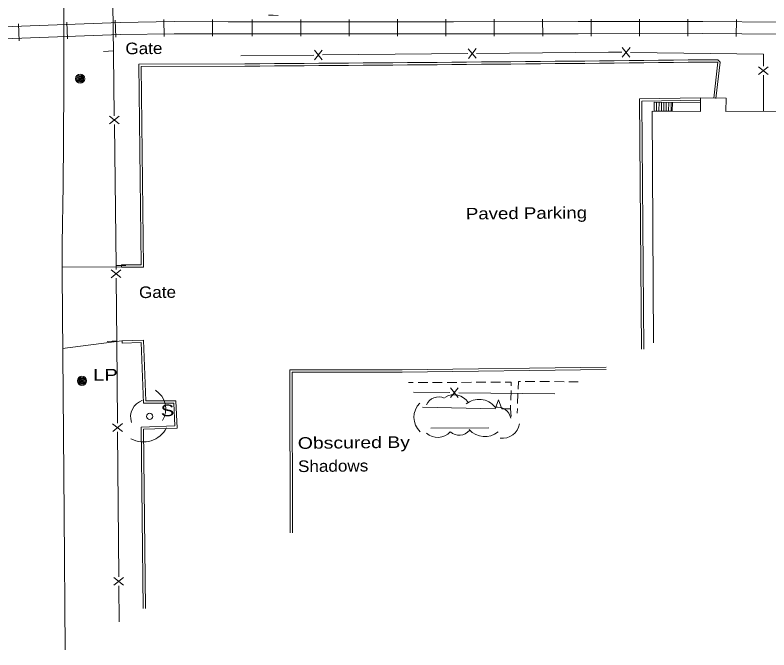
# Model space of a CAD drawing. Extents: x 2361284 to 2366480, y 6976556 to 6985346.
# Drawn here: x 2361689.4 to 2362001, y 6976992.8 to 6977255.3 of the extents above; entities that cross this region are included whole.
import ezdxf

# ---------------------------------------------------------------- set-up
doc = ezdxf.new("R2010")
doc.units = 0
doc.header["$LTSCALE"] = 1.9
for name, color, linetype, lineweight in [('11', 7, 'Continuous', 13), ('16', 7, 'Continuous', 13), ('19', 7, 'Continuous', 13), ('26', 7, 'Continuous', 13), ('28', 7, 'Continuous', 13), ('29', 7, 'Continuous', 13), ('3', 7, 'Continuous', 13), ('31', 7, 'Continuous', 13), ('4', 7, 'Continuous', 13), ('5', 7, 'Continuous', 13), ('7', 7, 'Continuous', 13), ('9', 7, 'Continuous', 13)]:
    doc.layers.add(name, color=color, linetype=linetype, lineweight=lineweight)

msp = doc.modelspace()

# ---------------------------------------------------------------- linework, layer by layer
at = {"layer": '11'}
msp.add_circle((2361745.02, 6977089.36), 1.3, dxfattribs=at)
at = {"layer": '16'}
for centre, radius, start, end in [((2361742.596, 6977092.433), 9.103, 328.01196, 58.01196), ((2361744.43, 6977089.118), 7.275, 108.25474, 198.25474), ((2361864.495, 6977091.789), 5.604, 65.33216, 155.33216), ((2361870.827, 6977091.313), 7.012, 32.34679, 122.34679), ((2361881.19, 6977087.978), 8.41, 39.00343, 129.00343), ((2361862.699, 6977089.017), 8.41, 135.70785, 225.70785), ((2361888.79, 6977087.607), 5.604, 10.97913, 100.97913), ((2361742.424, 6977089.717), 10.919, 242.07144, 332.07144), ((2361872.981, 6977087.197), 5.604, 229.38669, 319.38669), ((2361883.553, 6977089.37), 8.41, 220.60853, 310.60853), ((2361890.968, 6977087.35), 7.012, 261.38556, 351.38556), ((2361864.094, 6977087.684), 7.012, 227.98846, 317.98846)]:
    msp.add_arc(centre, radius, start, end, dxfattribs=at)
at = {"layer": '19'}
for p, q in [((2361852.002, 6977103.326), (2361854.002, 6977103.335)), ((2361856.002, 6977103.344), (2361860.002, 6977103.363)), ((2361862.002, 6977103.372), (2361866.003, 6977103.39)), ((2361868.003, 6977103.399), (2361872.003, 6977103.417)), ((2361874.003, 6977103.426), (2361878.002, 6977103.444)), ((2361880.002, 6977103.453), (2361884.002, 6977103.471)), ((2361886.002, 6977103.48), (2361890.003, 6977103.498)), ((2361900.311, 6977103.806), (2361904.311, 6977103.774)), ((2361906.31, 6977103.763), (2361910.312, 6977103.731)), ((2361912.312, 6977103.72), (2361916.313, 6977103.688)), ((2361918.313, 6977103.677), (2361922.093, 6977103.643)), ((2361894.397, 6977100.009), (2361894.285, 6977096.008)), ((2361897.147, 6977094.675), (2361897.279, 6977098.677)), ((2361894.224, 6977094.007), (2361894.179, 6977092.417)), ((2361897.005, 6977090.674), (2361897.076, 6977092.675))]:
    msp.add_line(p, q, dxfattribs=at)
for points in [[(2361892.003, 6977103.507), (2361894.503, 6977103.511), (2361894.458, 6977102.01)], [(2361897.35, 6977100.678), (2361897.45, 6977103.819), (2361898.311, 6977103.817)]]:
    msp.add_lwpolyline(points, dxfattribs=at)
at = {"layer": '26'}
msp.add_line((2361857.829, 6977093.181), (2361887.827, 6977092.547), dxfattribs=at)
for points in [[(2361887.827, 6977092.547), (2361889.223, 6977096.15), (2361890.588, 6977092.493)], [(2361890.598, 6977092.493), (2361894.179, 6977092.417), (2361894.398, 6977089.319)]]:
    msp.add_lwpolyline(points, dxfattribs=at)
at = {"layer": '28'}
for p, q in [((2361953.576, 6977219.288), (2361953.53, 6977215.708)), ((2361953.576, 6977219.288), (2361961.116, 6977219.2)), ((2361954.576, 6977219.278), (2361954.53, 6977215.697)), ((2361955.576, 6977219.267), (2361955.53, 6977215.687)), ((2361956.577, 6977219.247), (2361956.531, 6977215.666)), ((2361957.577, 6977219.236), (2361957.531, 6977215.656)), ((2361958.577, 6977219.226), (2361958.531, 6977215.645)), ((2361959.577, 6977219.215), (2361959.531, 6977215.635)), ((2361960.576, 6977219.195), (2361960.53, 6977215.614)), ((2361961.116, 6977219.2), (2361961.07, 6977215.62)), ((2361953.53, 6977215.708), (2361961.07, 6977215.62))]:
    msp.add_line(p, q, dxfattribs=at)
at = {"layer": '29'}
for p, q in [((2361710.807, 6977252.462), (2361711.063, 6977245.474)), ((2361730.801, 6977253.182), (2361731.047, 6977246.184)), ((2361750.908, 6977253.543), (2361751.025, 6977246.544)), ((2361771.019, 6977253.574), (2361771.005, 6977246.574)), ((2361787.471, 6977253.561), (2361787.477, 6977246.56)), ((2361807.472, 6977253.561), (2361807.478, 6977246.561)), ((2361827.472, 6977253.571), (2361827.479, 6977246.571)), ((2361847.474, 6977253.581), (2361847.481, 6977246.581)), ((2361867.475, 6977253.591), (2361867.482, 6977246.591)), ((2361887.476, 6977253.602), (2361887.482, 6977246.601)), ((2361907.476, 6977253.612), (2361907.482, 6977246.611)), ((2361927.477, 6977253.632), (2361927.484, 6977246.632)), ((2361947.478, 6977253.642), (2361947.475, 6977246.642)), ((2361967.479, 6977253.652), (2361967.476, 6977246.652)), ((2361987.532, 6977253.543), (2361987.469, 6977246.542)), ((2361690.813, 6977251.712), (2361691.079, 6977244.724))]:
    msp.add_line(p, q, dxfattribs=at)
for points in [[(2361502.388, 6977223.829), (2361520.924, 6977227.435), (2361539.462, 6977231.032), (2361564.028, 6977235.776), (2361588.624, 6977240.519), (2361605.934, 6977243.684), (2361623.379, 6977246.57), (2361638.949, 6977248.578), (2361654.61, 6977249.627), (2361678.726, 6977250.287), (2361680.815, 6977250.336), (2361706.777, 6977251.323), (2361732.821, 6977252.251), (2361755.178, 6977252.624), (2361777.5, 6977252.556)], [(2361777.48, 6977252.556), (2361824.032, 6977252.568), (2361870.585, 6977252.591), (2361922.127, 6977252.631), (2361973.699, 6977252.661), (2362006.034, 6977252.399), (2362038.331, 6977251.806)], [(2361503.334, 6977218.918), (2361521.871, 6977222.524), (2361540.409, 6977226.12), (2361564.975, 6977230.864), (2361589.541, 6977235.599), (2361606.791, 6977238.752), (2361624.106, 6977241.617), (2361639.437, 6977243.593), (2361654.838, 6977244.629), (2361667.906, 6977244.983), (2361680.972, 6977245.338), (2361706.955, 6977246.325), (2361732.948, 6977247.252), (2361755.206, 6977247.614), (2361777.477, 6977247.555)], [(2361777.477, 6977247.555), (2361824.029, 6977247.568), (2361870.582, 6977247.591), (2361922.124, 6977247.631), (2361973.676, 6977247.661), (2362005.961, 6977247.398), (2362038.238, 6977246.805)]]:
    msp.add_lwpolyline(points, dxfattribs=at)
at = {"layer": '3'}
for p, q in [((2361733.373, 6977151.022), (2361708.869, 6977151.269)), ((2361733.373, 6977151.022), (2361733.374, 6977151.982)), ((2361733.563, 6977120.561), (2361709.092, 6977117.408)), ((2361733.692, 6977119.612), (2361733.653, 6977120.572)), ((2361933.786, 6977109.694), (2361849.333, 6977108.561)), ((2361933.795, 6977108.734), (2361849.342, 6977107.601))]:
    msp.add_line(p, q, dxfattribs=at)
for points in [[(2361709.263, 6977380.134), (2361708.329, 6977367.291), (2361707.952, 6977360.87), (2361707.542, 6977351.237), (2361707.362, 6977341.602), (2361707.374, 6977336.784), (2361707.501, 6977329.848), (2361708.007, 6977315.976), (2361709.246, 6977288.229), (2361709.529, 6977274.351), (2361709.615, 6977226.968), (2361709.504, 6977203.277), (2361709.238, 6977185.014), (2361708.851, 6977160.664), (2361708.835, 6977148.488), (2361709.644, 6977048.779), (2361710.137, 6976992.762)], [(2361979.827, 6977236.889), (2361980.79, 6977235.819), (2361979.112, 6977220.881)], [(2361733.373, 6977151.022), (2361742.453, 6977151.018), (2361741.473, 6977234.033), (2361784.455, 6977234.202)], [(2361733.374, 6977151.982), (2361741.484, 6977151.979), (2361740.504, 6977234.994), (2361784.456, 6977235.162)], [(2361979.837, 6977235.929), (2361979.839, 6977235.93), (2361978.161, 6977220.992)], [(2361972.699, 6977221.05), (2361947.491, 6977220.731), (2361948.276, 6977117.192)], [(2361972.708, 6977220.09), (2361948.46, 6977219.78), (2361949.236, 6977117.202)], [(2361743.264, 6977009.947), (2361742.55, 6977084.005), (2361756.437, 6977084.487), (2361755.889, 6977095.802), (2361743.468, 6977095.764), (2361742.459, 6977120.936), (2361733.653, 6977120.572)], [(2361742.304, 6977009.938), (2361741.581, 6977084.936), (2361755.428, 6977085.417), (2361754.978, 6977094.844), (2361742.547, 6977094.805), (2361741.538, 6977119.937), (2361733.692, 6977119.612)], [(2361849.353, 6977108.561), (2361803, 6977108.551), (2361803.15, 6977041.219)], [(2361849.352, 6977107.601), (2361803.959, 6977107.59), (2361804.11, 6977041.218)]]:
    msp.add_lwpolyline(points, dxfattribs=at)
for radius in [51744.577, 51745.537]:
    msp.add_arc((2361424.566, 7028978.487), radius, 270.39849, 270.61484, dxfattribs=at)
at = {"layer": '31'}
msp.add_line((2361961.116, 6977219.2), (2361972.725, 6977219.37), dxfattribs=at)
at = {"layer": '4'}
for centre, radius in [((2361716.31, 6977229.023), 1.9), ((2361716.31, 6977229.023), 1.442), ((2361716.31, 6977229.023), 0.539), ((2361716.31, 6977229.023), 0.192), ((2361717.058, 6977104.073), 1.9), ((2361717.058, 6977104.073), 1.442), ((2361717.058, 6977104.073), 0.539), ((2361717.058, 6977104.073), 0.192)]:
    msp.add_circle(centre, radius, dxfattribs=at)
for centre, start, end in [((2361716.31, 6977229.023), 107.21593, 118.46597), ((2361716.31, 6977229.023), 95.96582, 107.21585), ((2361716.31, 6977229.023), 84.71553, 95.96557), ((2361716.31, 6977229.023), 73.46552, 84.71555), ((2361716.31, 6977229.023), 62.21535, 73.46538), ((2361716.31, 6977229.023), 174.71552, 185.96556), ((2361716.31, 6977229.023), 163.46611, 174.71615), ((2361716.31, 6977229.023), 185.96287, 197.21291), ((2361716.31, 6977229.023), 152.21535, 163.46538), ((2361716.31, 6977229.023), 197.21479, 208.46483), ((2361716.31, 6977229.023), 140.96646, 152.21649), ((2361716.31, 6977229.023), 208.46822, 219.71826), ((2361716.31, 6977229.023), 129.71376, 140.96379), ((2361716.31, 6977229.023), 219.71376, 230.96379), ((2361716.31, 6977229.023), 118.46406, 129.71409), ((2361716.31, 6977229.023), 230.96397, 242.214), ((2361716.31, 6977229.023), 242.21812, 253.46815), ((2361716.31, 6977229.023), 253.46258, 264.71261), ((2361716.31, 6977229.023), 264.71553, 275.96557), ((2361716.31, 6977229.023), 275.96582, 287.21585), ((2361716.31, 6977229.023), 287.21593, 298.46597), ((2361716.31, 6977229.023), 50.96397, 62.214), ((2361716.31, 6977229.023), 298.46406, 309.71409), ((2361716.31, 6977229.023), 39.71588, 50.96591), ((2361716.31, 6977229.023), 309.71589, 320.96592), ((2361716.31, 6977229.023), 28.46656, 39.7166), ((2361716.31, 6977229.023), 320.96646, 332.21649), ((2361716.31, 6977229.023), 17.21479, 28.46483), ((2361716.31, 6977229.023), 332.21419, 343.46422), ((2361716.31, 6977229.023), 5.96345, 17.21348), ((2361716.31, 6977229.023), 343.46611, 354.71615), ((2361716.31, 6977229.023), 354.71553, 5.96557), ((2361717.058, 6977104.073), 174.71552, 185.96556), ((2361717.058, 6977104.073), 163.46611, 174.71615), ((2361717.058, 6977104.073), 185.96287, 197.21291), ((2361717.058, 6977104.073), 152.21535, 163.46538), ((2361717.058, 6977104.073), 197.21479, 208.46483), ((2361717.058, 6977104.073), 140.96646, 152.21649), ((2361717.058, 6977104.073), 208.46822, 219.71826), ((2361717.058, 6977104.073), 129.71376, 140.96379), ((2361717.058, 6977104.073), 219.71376, 230.96379), ((2361717.058, 6977104.073), 118.46406, 129.71409), ((2361717.058, 6977104.073), 230.96397, 242.214), ((2361717.058, 6977104.073), 107.21593, 118.46597), ((2361717.058, 6977104.073), 242.21812, 253.46815), ((2361717.058, 6977104.073), 95.96582, 107.21585), ((2361717.058, 6977104.073), 253.46258, 264.71261), ((2361717.058, 6977104.073), 84.71553, 95.96557), ((2361717.058, 6977104.073), 264.71553, 275.96557), ((2361717.058, 6977104.073), 73.46552, 84.71555), ((2361717.058, 6977104.073), 275.96582, 287.21585), ((2361717.058, 6977104.073), 62.21535, 73.46538), ((2361717.058, 6977104.073), 287.21593, 298.46597), ((2361717.058, 6977104.073), 50.96397, 62.214), ((2361717.058, 6977104.073), 298.46406, 309.71409), ((2361717.058, 6977104.073), 39.71588, 50.96591), ((2361717.058, 6977104.073), 309.71589, 320.96592), ((2361717.058, 6977104.073), 28.46656, 39.7166), ((2361717.058, 6977104.073), 320.96646, 332.21649), ((2361717.058, 6977104.073), 17.21479, 28.46483), ((2361717.058, 6977104.073), 332.21419, 343.46422), ((2361717.058, 6977104.073), 5.96345, 17.21348), ((2361717.058, 6977104.073), 343.46611, 354.71615), ((2361717.058, 6977104.073), 354.71553, 5.96557)]:
    msp.add_arc(centre, 0.973, start, end, dxfattribs=at)
at = {"layer": '5'}
for points in [[(2361798.104, 6977255.174), (2361796.115, 6977255.243), (2361794.116, 6977255.313)], [(2361730.009, 6977240.535), (2361728.025, 6977240.374), (2361726.032, 6977240.213)], [(2361731.163, 6977151.742), (2361733.153, 6977151.743), (2361735.153, 6977151.744)], [(2361731.512, 6977120.463), (2361729.522, 6977120.426), (2361727.523, 6977120.388)]]:
    msp.add_lwpolyline(points, dxfattribs=at)
at = {"layer": '7'}
msp.add_line((2361885.232, 6977084.582), (2361861.291, 6977084.534), dxfattribs=at)
msp.add_lwpolyline([(2362038.189, 6977263.566), (2362038.324, 6977215.694), (2361983.194, 6977215.48), (2361983.362, 6977220.932), (2361972.699, 6977221.05), (2361972.772, 6977215.491), (2361952.731, 6977215.63), (2361953.282, 6977119.78)], dxfattribs=at)
at = {"layer": '9'}
for p, q in [((2361813.143, 6977240.784), (2361816.381, 6977236.816)), ((2361816.343, 6977240.815), (2361813.181, 6977236.785)), ((2361876.549, 6977239.448), (2361816.552, 6977238.848)), ((2361876.74, 6977241.419), (2361879.978, 6977237.45)), ((2361879.94, 6977241.449), (2361876.778, 6977237.42)), ((2361943.58, 6977241.884), (2361940.327, 6977237.924)), ((2361940.379, 6977241.924), (2361943.528, 6977237.885)), ((2361812.952, 6977238.813), (2361782.764, 6977238.506)), ((2362000.689, 6977230.737), (2361996.688, 6977233.94)), ((2362000.689, 6977233.938), (2361996.688, 6977230.739)), ((2361998.704, 6977215.537), (2361998.721, 6977230.538)), ((2361732.459, 6977210.346), (2361728.418, 6977213.507)), ((2361732.419, 6977213.545), (2361728.458, 6977210.308)), ((2361733.194, 6977146.75), (2361729.153, 6977149.912)), ((2361733.153, 6977149.95), (2361729.193, 6977146.712)), ((2361854.16, 6977099.347), (2361869.163, 6977099.179)), ((2361869.342, 6977097.201), (2361872.585, 6977101.162)), ((2361872.533, 6977097.171), (2361869.384, 6977101.202)), ((2361872.764, 6977099.134), (2361912.49, 6977098.681)), ((2361733.779, 6977083.151), (2361729.757, 6977086.313)), ((2361733.758, 6977086.351), (2361729.778, 6977083.113)), ((2361732.291, 6977022.934), (2361731.811, 6977082.933)), ((2361734.283, 6977019.552), (2361730.262, 6977022.714)), ((2361734.263, 6977022.752), (2361730.282, 6977019.514)), ((2361732.438, 6977004.334), (2361732.315, 6977019.334))]:
    msp.add_line(p, q, dxfattribs=at)
for points in [[(2361730.446, 6977213.727), (2361730.153, 6977239.306), (2361729.874, 6977260.164), (2361743.076, 6977263.25)], [(2361940.148, 6977239.953), (2361934.737, 6977240.031), (2361880.149, 6977239.482)], [(2361998.727, 6977234.139), (2361998.729, 6977239.16), (2361943.749, 6977239.907)], [(2361731.182, 6977150.131), (2361731.168, 6977151.441), (2361730.49, 6977210.127)], [(2361731.786, 6977086.533), (2361731.515, 6977120.282), (2361731.226, 6977146.531)]]:
    msp.add_lwpolyline(points, dxfattribs=at)

# ---------------------------------------------------------------- texts
at = {"layer": '11', "width": 1.3}
msp.add_text('  S', height=4.799, rotation=0.545, dxfattribs=at).set_placement((2361745.019, 6977089.359))
at = {"layer": '3', "width": 1.2}
msp.add_text('Paved Parking', height=4.799, rotation=0.545, dxfattribs=at).set_placement((2361875.763, 6977170.786))
at = {"layer": '4', "width": 1.3}
msp.add_text('  LP', height=4.799, rotation=0.545, dxfattribs=at).set_placement((2361717.058, 6977104.073))
at = {"layer": '7'}
for s, width, p in [('Obscured By', 1.25, (2361806.291, 6977075.92)), ('Shadows', 1.1, (2361806.382, 6977066.321))]:
    msp.add_text(s, height=4.799, rotation=0.545, dxfattribs=dict(at, width=width)).set_placement(p)
at = {"layer": '9', "width": 1.1}
for p in [(2361735.036, 6977239.112), (2361740.664, 6977138.279)]:
    msp.add_text('Gate', height=4.799, rotation=0.545, dxfattribs=at).set_placement(p)

doc.saveas('drawing.dxf')
